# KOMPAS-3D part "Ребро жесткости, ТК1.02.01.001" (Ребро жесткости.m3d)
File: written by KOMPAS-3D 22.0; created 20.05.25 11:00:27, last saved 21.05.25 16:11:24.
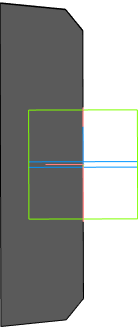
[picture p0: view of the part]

Document properties: Автор: TC; Полное имя файла: ТК1.02.01.001 - Ребро жесткости.cdw

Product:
- Part/product: Ребро жесткости  | designation ТК1.02.01.001
    Материал: Сталь 09Г2С ГОСТ 19281-2014 (density 7850 kg/m3)
    Масса: 0.212581
    Форматы листов документа: A4

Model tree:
1. Эскиз:1
2. Элемент выдавливания:1  (labels: Сталь 09Г2С ГОСТ 19281-2014; BOSimple***Material:4ccf0190-16b6-4223-9222-aa108d28a442)
     Расстояние 1 = 5

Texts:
  ТК1.02.01.001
